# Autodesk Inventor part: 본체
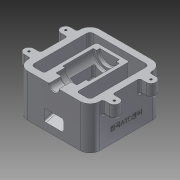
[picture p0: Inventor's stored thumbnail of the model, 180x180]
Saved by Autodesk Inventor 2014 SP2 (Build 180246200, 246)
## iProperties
Created: 2018-01
Part Number: 본체
Material: 알루미늄 6061
Document SubType Name: Modeling
Designer: 거성
Density: 2.71 g/cm^3
Appearance: 알루미늄 - 평지
Mass: 1031.84 g
Surface Area: 853.24 cm^2
Volume: 380.754 cm^3
Author: 거성
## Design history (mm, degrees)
sketch "스케치1"
  geometry: L1 (55, 55)-(-55, 55); L2 (-55, 55)-(-55, -55); L3 (-55, -55)-(55, -55); L4 (55, -55)-(55, 55); L5 (45, 45)-(-45, 45); L6 (-45, 45)-(-45, -45); L7 (-45, -45)-(45, -45); L8 (45, -45)-(45, 45); 5 further points
  constraints: 16 end point, 4 midpoint, 4 parallel, 2 horizontal, 2 horizontal alignment, 2 perpendicular, 2 vertical alignment
  dimensions: "d0" = 110 distance of L1.end L2.end; "d1" = 110 distance of L2.end L3.end; "d2" = 10 distance between parallel lines of L3 L7; "d3" = 10 distance between parallel lines of L4 L8
extrude "돌출1" new body sketch "스케치1" distance "d4" = 65; taper "d5" = 0 deg
sketch "스케치2"
  geometry: L1 (0, 0)-(110, 0) reference; L2 (0, 0)-(0, 65) reference; 2 further points
  constraints: 1 other
  dimensions: "d6" = 55 distance from line of point (55, 20) L2; "d7" = 20 distance from line of point (55, 20) L1
feature "엠보싱1" sketch "스케치2" dims "d0" = 110, "d1" = 110, "d2" = 10, "d3" = 10, "d8" = 0.5, "d9" = 0
sketch "스케치3"
  geometry: L1 (-55, -55)-(55, -55) reference; L2 (-55, 55)-(-55, -55) reference; L3 (-65, -35.5)-(-55, -35.5); L4 (-65, -20.5)-(-55, -20.5); L5 (-55, -20.5)-(-55, -35.5); A1 r 7.5 centre (-65, -28) between (-65, -35.5) and (-65, -20.5); 1 further point
  constraints: 6 end point, 2 perpendicular, 2 point on circle, 2 point on line, 2 tangent, 1 centre point, 1 collinear
  dimensions: "d10" = 7.5 radius of A1; "d11" = 27 distance from line of A1.centre L1; "d12" = 10 distance from line of A1.centre L2
extrude "돌출2" join sketch "스케치3" distance "d13" = 20; taper "d14" = 0 deg
sketch "스케치4"
  geometry: A1 r 7.5 centre (-65, -28) between (-65, -20.5) and (-65, -35.5) reference; 2 further points
  constraints: 1 coincident
hole "구멍1" sketch "스케치4" at (-65, -28) diameter "d15" = 3.242; stored, may be unused: countersink angle "d19" = 90 deg, drill point angle "d21" = 118 deg; dims "d16" = 9, "d17" = 4, "d18" = 2, "d20" = 11
node "작업 평면1"
sketch "스케치5"
  geometry: L1 (0, 45)-(65, 45) reference; L2 (8.564, 45)-(30, -35); L3 (65, 45)-(65, -45) reference; L4 (30, -35)-(65, -35); L5 (0, -45)-(0, 45) reference; L6 (0, -55)-(65, -55) reference; 1 further point
  constraints: 4 end point, 2 point on line, 1 perpendicular
  dimensions: "d26" = 105 deg angle of L1 L2; "d27" = 30 distance from line of L2.end L5; "d28" = 20 distance between parallel lines of L4 L6
extrude "돌출3" join sketch "스케치5" stored distance "d29" = 50; taper "d30" = 0 deg
node "작업 평면2"
sketch "스케치6"
  geometry: L1 (65, 45)-(65, -35) reference; L2 (65, 55)-(65, -35); L3 (57.5, 55)-(57.5, 36); L4 (57.5, 36)-(49, 36); L5 (49, 36)-(49, 22); L6 (49, 22)-(45, 22); L7 (45, 22)-(45, -25); L8 (45, -25)-(50, -25); L9 (50, -25)-(50, -30); L10 (50, -30)-(65, -30); L11 (0, 55)-(65, 55) reference; L12 (57.5, 55)-(65, 55); 2 further points
  constraints: 20 end point, 6 parallel, 2 collinear, 2 perpendicular, 1 horizontal alignment, 1 midpoint, 1 point on line
  dimensions: "d32" = 15 diameter of L3 L2; "d33" = 32 diameter of L5 L2; "d34" = 40 diameter of L7 L2; "d35" = 30 diameter of L9 L2; "d36" = 19 distance between parallel lines of L4 L11; "d37" = 14 distance between parallel lines of L6 L4; "d38" = 47 distance between parallel lines of L8 L6; "d39" = 5 distance between parallel lines of L10 L8
revolve "회전1" sketch "스케치6" stored, may be unused: angle "d40" = 90 deg
node "작업 평면3"
sketch "스케치7"
  geometry: L1 (0, 55)-(65, 55) reference; L2 (45, 22)-(45, -25) reference; L3 (30, -35)-(8.564, 45) reference; L4 (11.061, 55)-(31.157, -20); L5 (31.157, -20)-(45, -20); L6 (45, 17)-(39.243, 17); L7 (39.243, 17)-(29.061, 55); L8 (45, 22)-(65, 22) reference; L9 (45, 17)-(50, 17); L10 (50, 17)-(50, -20); L11 (50, -20)-(45, -20); 1 further point
  constraints: 14 end point, 4 point on line, 3 parallel, 3 perpendicular
  dimensions: "d42" = 5 distance from line of L3.end L4; "d44" = 37 distance between parallel lines of L6 L5; "d45" = 75 deg angle of L1 L7; "d46" = 18 distance of L7.end L4.start; "d47" = 5 distance between parallel lines of L6 L8; "d48" = 5 distance of L6.start L9.end
extrude "돌출4" cut sketch "스케치7" stored distance "d49" = 30; taper "d50" = 0 deg
chamfer "모따기1" distance "d51" = 1; stored, may be unused: second distance "d52" = 2, angle "d53" = 45 deg
fillet "모깎기1" dims "d54" = 15, "d55" = 5, "d56" = 3, "d57" = 1, "d58" = 3, "d62" = 3
fillet "모깎기2" dims "d59" = 3, "d60" = 3, "d63" = 3
node "솔리드1"
pattern_linear "직사각형 패턴1" dims "d24" = 56
mirror "대칭1"
other parameters: "d25" = 0, "d31" = 0, "d41" = 0
